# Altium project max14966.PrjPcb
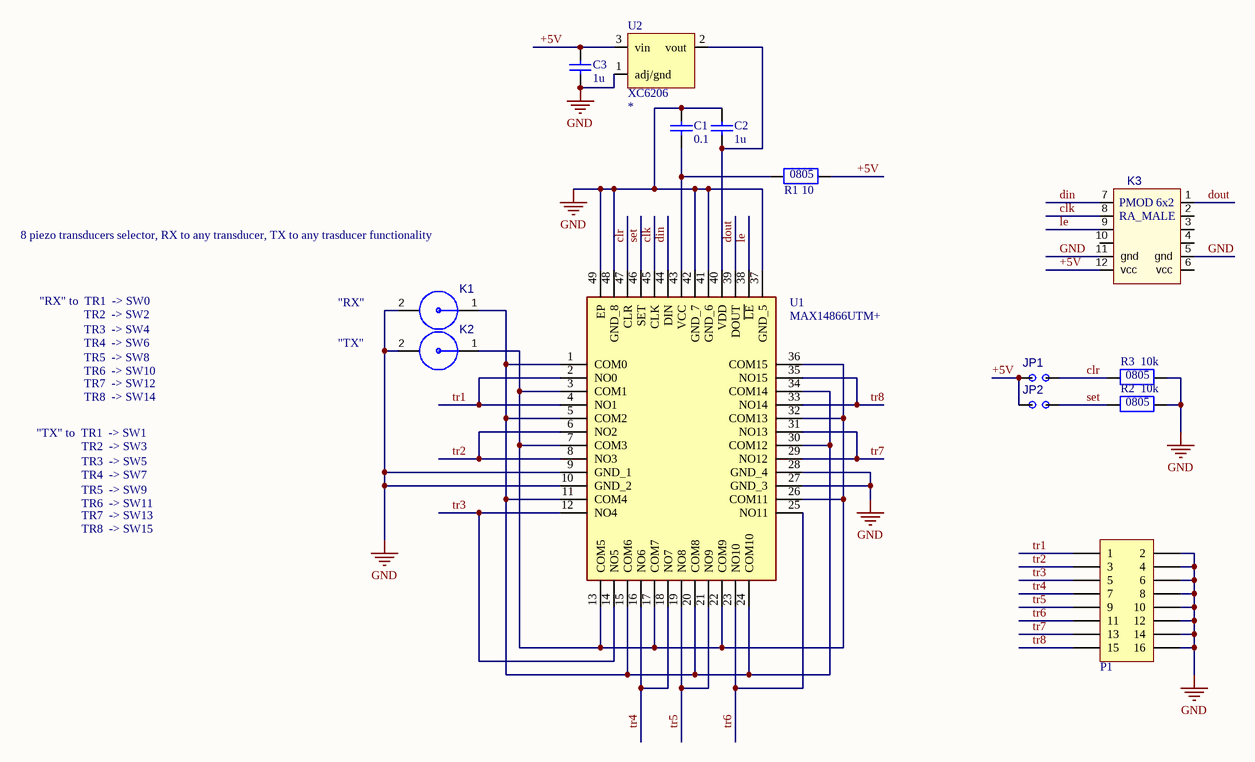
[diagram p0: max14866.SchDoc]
1 sheet, 14 parts. Net scope: global (net labels, ports and power ports of the same name join across sheets).
Board file: max.PcbDoc

## Sheet max14866.SchDoc
size A4

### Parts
C1  value 0.1  [SM0805]  (hidden comment: cap0805)
C2  value 1u  [SM0805]  (hidden comment: cap0805)
C3  value 1u  [SM0805]  (hidden comment: cap0805)
JP1  JUMPER2  [JUMPER2]  (value not drawn)
JP2  JUMPER2  [JUMPER2]  (value not drawn)
K1  SMA_MALE_FEMALE  [AMPHENOL_MALE _FEMALE]  (value not drawn)
K2  SMA_MALE_FEMALE  [AMPHENOL_MALE _FEMALE]  (value not drawn)
K3  PMOD_6x2_ra_male_mirrored  [PMOD_6x2_RA_MALE_MIRRORED]  (value not drawn)
P1  2x8, 2.54mm vertical  [2x8 pin 2.54mm]  (value not drawn)
R1  value 10  [SM0805]  (hidden comment: res0805_EU)
R2  value 10k  [SM0805]  (hidden comment: res0805_EU)
R3  value 10k  [SM0805]  (hidden comment: res0805_EU)
U1  MAX14866UTM+  [QFN50P700X700X80-49N]
U2  XC6206  [SOT-23]

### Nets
GND: C1.2 C2.2 C3.1 K1.2 K2.2 K3.5(gnd) K3.11(gnd) P1.2 P1.4 P1.6 P1.8 P1.10 P1.12 P1.14 P1.16 R2.2 R3.2 U1.9(GND_1) U1.10(GND_2) U1.27(GND_3) U1.28(GND_4) U1.37(GND_5) U1.41(GND_6) U1.42(GND_7) U1.48(GND_8) U1.49(EP) U2.1(adj/gnd)
+5V: C3.2 JP1.2 JP2.2 K3.12(vcc) R1.2 U2.3(vin)
clk: K3.8 U1.45(CLK)
clr: JP1.1 R3.1 U1.47(CLR)
din: K3.7 U1.44(DIN)
dout: K3.1 U1.39(DOUT)
le: K3.9 U1.38(~{LE})
set: JP2.1 R2.1 U1.46(SET)
tr1: P1.1 U1.2(NO0) U1.4(NO1)
tr2: P1.3 U1.6(NO2) U1.8(NO3)
tr3: P1.5 U1.12(NO4) U1.14(NO5)
tr4: P1.7 U1.16(NO6) U1.18(NO7)
tr5: P1.9 U1.19(NO8) U1.21(NO9)
tr6: P1.11 U1.23(NO10) U1.25(NO11)
tr7: P1.13 U1.29(NO12) U1.31(NO13)
tr8: P1.15 U1.33(NO14) U1.35(NO15)
NetC1_1: C1.1 R1.1 U1.43(VCC)
NetC2_1: C2.1 U1.40(VDD) U2.2(vout)
NetK1_1: K1.1 U1.1(COM0) U1.5(COM2) U1.11(COM4) U1.15(COM6) U1.20(COM8) U1.24(COM10) U1.30(COM12) U1.34(COM14)
NetK2_1: K2.1 U1.3(COM1) U1.7(COM3) U1.13(COM5) U1.17(COM7) U1.22(COM9) U1.26(COM11) U1.32(COM13) U1.36(COM15)

Not connected (* = marked no-connect by the designer): K3 2 3 4 6(vcc) 10

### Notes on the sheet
- 8 piezo transducers selector, RX to any transducer, TX to any trasducer functionality
- "RX" to  TR1  -> SW0
- TR2  -> SW2
- TR3  -> SW4
- TR4  -> SW6
- TR5  -> SW8
- "TX"
- "RX"
- TR6  -> SW10
- TR7  -> SW12
- TR8  -> SW14
- "TX" to  TR1  -> SW1
- TR2  -> SW3
- TR3  -> SW5
- TR4  -> SW7
- TR5  -> SW9
- TR6  -> SW11
- TR7  -> SW13
- TR8  -> SW15

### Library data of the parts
C1-C3 = cap0805: Capacitor
K3 = PMOD_6x2_ra_male_mirrored: PMOD_6x2_right_angle
P1 = 2x8, 2.54mm, vertical: Header, 16-Pin
R1-R3 = res0805_EU: Resistor
U1 = MAX14866UTM+: Integrated Circuit; Manufacturer_Name: Maxim Integrated
U2 = XC6206: SOT-23-3 ldo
